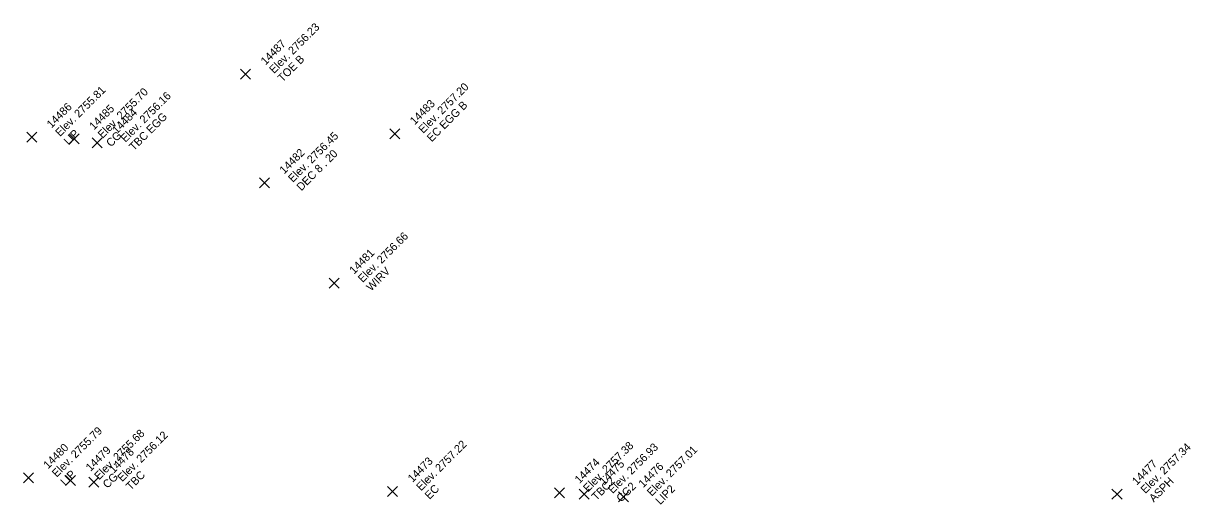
# Model space of a CAD drawing. Extents: x 2493999 to 2503109, y 700767 to 706646.
# Drawn here: x 2502321.91 to 2502356.9, y 703476.78 to 703491.21 of the extents above; entities that cross this region are included whole.
import ezdxf

# ---------------------------------------------------------------- set-up
doc = ezdxf.new("R2010")
doc.units = 0
doc.layers.add('ALG_CL_BLUE_Horiz', color=7, linetype='Continuous')
doc.layers.add('DES_SURFACE_Existing-Ground', color=7, linetype='Continuous')

msp = doc.modelspace()

# ---------------------------------------------------------------- linework, layer by layer
at = {"layer": 'ALG_CL_BLUE_Horiz'}
for points in [[(2502328.568, 703489.691), (2502328.418, 703489.841), (2502328.568, 703489.691), (2502328.418, 703489.541), (2502328.568, 703489.691), (2502328.718, 703489.541), (2502328.568, 703489.691), (2502328.718, 703489.841)], [(2502322.155, 703487.799), (2502322.005, 703487.949), (2502322.155, 703487.799), (2502322.005, 703487.649), (2502322.155, 703487.799), (2502322.305, 703487.649), (2502322.155, 703487.799), (2502322.305, 703487.949)], [(2502333.04, 703487.896), (2502332.89, 703488.046), (2502333.04, 703487.896), (2502332.89, 703487.746), (2502333.04, 703487.896), (2502333.19, 703487.746), (2502333.04, 703487.896), (2502333.19, 703488.046)], [(2502323.428, 703487.745), (2502323.278, 703487.895), (2502323.428, 703487.745), (2502323.278, 703487.595), (2502323.428, 703487.745), (2502323.578, 703487.595), (2502323.428, 703487.745), (2502323.578, 703487.895)], [(2502324.115, 703487.627), (2502323.965, 703487.777), (2502324.115, 703487.627), (2502323.965, 703487.477), (2502324.115, 703487.627), (2502324.265, 703487.477), (2502324.115, 703487.627), (2502324.265, 703487.777)], [(2502329.133, 703486.425), (2502328.983, 703486.575), (2502329.133, 703486.425), (2502328.983, 703486.275), (2502329.133, 703486.425), (2502329.283, 703486.275), (2502329.133, 703486.425), (2502329.283, 703486.575)], [(2502331.226, 703483.419), (2502331.076, 703483.569), (2502331.226, 703483.419), (2502331.076, 703483.269), (2502331.226, 703483.419), (2502331.376, 703483.269), (2502331.226, 703483.419), (2502331.376, 703483.569)], [(2502322.055, 703477.579), (2502321.905, 703477.729), (2502322.055, 703477.579), (2502321.905, 703477.429), (2502322.055, 703477.579), (2502322.205, 703477.429), (2502322.055, 703477.579), (2502322.205, 703477.729)], [(2502323.323, 703477.502), (2502323.173, 703477.652), (2502323.323, 703477.502), (2502323.173, 703477.352), (2502323.323, 703477.502), (2502323.473, 703477.352), (2502323.323, 703477.502), (2502323.473, 703477.652)], [(2502324.019, 703477.448), (2502323.869, 703477.598), (2502324.019, 703477.448), (2502323.869, 703477.298), (2502324.019, 703477.448), (2502324.169, 703477.298), (2502324.019, 703477.448), (2502324.169, 703477.598)], [(2502332.975, 703477.173), (2502332.825, 703477.323), (2502332.975, 703477.173), (2502332.825, 703477.023), (2502332.975, 703477.173), (2502333.125, 703477.023), (2502332.975, 703477.173), (2502333.125, 703477.323)], [(2502337.979, 703477.135), (2502337.829, 703477.285), (2502337.979, 703477.135), (2502337.829, 703476.985), (2502337.979, 703477.135), (2502338.129, 703476.985), (2502337.979, 703477.135), (2502338.129, 703477.285)], [(2502338.72, 703477.09), (2502338.57, 703477.24), (2502338.72, 703477.09), (2502338.57, 703476.94), (2502338.72, 703477.09), (2502338.87, 703476.94), (2502338.72, 703477.09), (2502338.87, 703477.24)], [(2502339.893, 703477.011), (2502339.743, 703477.161), (2502339.893, 703477.011), (2502339.743, 703476.861), (2502339.893, 703477.011), (2502340.043, 703476.861), (2502339.893, 703477.011), (2502340.043, 703477.161)], [(2502354.688, 703477.09), (2502354.538, 703477.24), (2502354.688, 703477.09), (2502354.538, 703476.94), (2502354.688, 703477.09), (2502354.838, 703476.94), (2502354.688, 703477.09), (2502354.838, 703477.24)]]:
    msp.add_lwpolyline(points, dxfattribs=at)

# ---------------------------------------------------------------- texts
at = {"layer": 'DES_SURFACE_Existing-Ground'}
for s, p in [('Elev. 2756.23', (2502329.417, 703489.691)), ('14487', (2502329.162, 703489.946)), ('TOE B', (2502329.671, 703489.436)), ('Elev. 2755.81', (2502323.004, 703487.799)), ('Elev. 2757.20', (2502333.889, 703487.896)), ('Elev. 2755.70', (2502324.277, 703487.745)), ('Elev. 2756.16', (2502324.964, 703487.627)), ('14486', (2502322.749, 703488.054)), ('14485', (2502324.022, 703488)), ('14484', (2502324.709, 703487.882)), ('14483', (2502333.634, 703488.151)), ('EC EGG B', (2502334.143, 703487.641)), ('TBC EGG', (2502325.218, 703487.372)), ('LIP', (2502323.258, 703487.544)), ('CG', (2502324.531, 703487.49)), ('Elev. 2756.45', (2502329.982, 703486.425)), ('14482', (2502329.727, 703486.68)), ('DEC 8 . 20', (2502330.236, 703486.17)), ('Elev. 2756.66', (2502332.075, 703483.419)), ('14481', (2502331.82, 703483.674)), ('WIRV', (2502332.329, 703483.164)), ('Elev. 2755.79', (2502322.904, 703477.579)), ('Elev. 2755.68', (2502324.172, 703477.502)), ('Elev. 2756.12', (2502324.868, 703477.448)), ('14480', (2502322.649, 703477.834)), ('14479', (2502323.917, 703477.757)), ('14478', (2502324.613, 703477.703)), ('Elev. 2757.22', (2502333.824, 703477.173)), ('Elev. 2757.38', (2502338.828, 703477.135)), ('Elev. 2756.93', (2502339.569, 703477.09)), ('Elev. 2757.01', (2502340.742, 703477.011)), ('Elev. 2757.34', (2502355.537, 703477.09)), ('14473', (2502333.569, 703477.428)), ('14474', (2502338.573, 703477.39)), ('14475', (2502339.314, 703477.345)), ('14477', (2502355.282, 703477.345)), ('LIP', (2502323.158, 703477.324)), ('TBC', (2502325.122, 703477.193)), ('14476', (2502340.487, 703477.266)), ('CG', (2502324.426, 703477.247)), ('TBC2', (2502339.082, 703476.88)), ('CG2', (2502339.823, 703476.835)), ('ASPH', (2502355.791, 703476.835)), ('EC', (2502334.078, 703476.918)), ('LIP2', (2502340.996, 703476.756))]:
    msp.add_text(s, height=0.24, rotation=45, dxfattribs=at).set_placement(p)

doc.saveas('drawing.dxf')
